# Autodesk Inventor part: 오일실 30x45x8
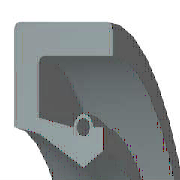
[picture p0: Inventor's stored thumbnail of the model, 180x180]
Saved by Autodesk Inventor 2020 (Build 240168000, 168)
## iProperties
Created: 2012-02
Part Number: 오일실 30x45x8
Material: 고무
Document SubType Name: Modeling
Standard: JIS B 2402
Designer: mdu-01
Standards Organization: JIS
Language: ko-KR
Size Designation: 30 45 8 A
Categories: <MemberInstance><Categories><Category DisplayName="샤프트 부품" InternalName="7f7aeb1f-a693-4053-b835-cee3144e0d98" Mnemonic="SHFT"><Category DisplayName="실링" Intern
Density: 0.93 g/cm^3
Appearance: Rubber-Black
IsCustomPart: 1
Author: mdu-01
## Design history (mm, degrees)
body "Solid1"
revolve "회전1" stored, may be unused: angle "d33" = 360 deg
fillet "모깎기1" dims "d34" = 0.4 (= 0.05 x b)
sketch "스케치2"
  geometry: L1 (16.821, -5.895)-(17.526, -8); L2 (16.071, -5.2)-(16.821, -5.895); L3 (15, -2)-(16.071, -5.2); L4 (16, -1)-(15, -2); L5 (17.676, -1)-(16, -1); L6 (17.676, -1.8)-(17.676, -1); L7 (17.676, -6)-(17.676, -3.4); L8 (19.5, -6)-(17.676, -6); L9 (21, -2)-(19.5, -6); L10 (21, 0)-(21, -2); L11 (22.5, 0)-(21, 0); L12 (22.5, -8)-(22.5, 0); L13 (17.526, -8)-(22.5, -8); L14 (0, -9.6)-(0, 1.6) reference; L15 (28, 0)-(14, 0) reference; A1 r 0.8 centre (17.676, -2.6) between (17.676, -3.4) and (17.676, -1.8)
  constraints: 26 end point, 4 horizontal, 4 vertical, 2 point on circle, 1 centre point, 1 collinear, 1 parallel
  dimensions: "d2" = 8 distance of L12.start L11.start (= b); "d4" = 1 vertical distance of L10.start L5.start (= 0.125 x b); "d6" = 1.5 distance of L11.start L10.start (= 0.1 x dd - 0.1 x Diam); "d8" = 2 distance of L10.start L9.start (= 0.25 x b); "d10" = 2 vertical distance of L8.start L1.end (= 0.25 x b); "d12" = 1.5 horizontal distance of L9.start L8.start (= 0.1 x dd - 0.1 x Diam); "d14" = 0.8 radius of A1 (= 0.1 x b); "d16" = 0 horizontal distance of A1.centre L7.end; "d18" = 0.8 distance of L6.start L5.start (= 0.1 x b); "d20" = 1 horizontal distance of L4.start L3.start (= 0.0666667 x dd - 0.0666667 x Diam); "d22" = 0.15 horizontal distance of L7.start L1.end (= 0.01 x dd - 0.01 x Diam); "d24" = 1 horizontal distance of L4.start L3.start (= 0.125 x b); "d26" = 3.2 vertical distance of L3.start L2.start (= 0.4 x b); "d28" = 1.07143 horizontal distance of L3.start L2.start (= 0.0714286 x dd - 0.0714286 x Diam); "d30" = 2.10526 vertical distance of L1.start L1.end (= 0.263158 x b); "d32" = 0.75 horizontal distance of L2.start L1.start (= 0.05 x dd - 0.05 x Diam); "d37" = 0 distance between parallel lines of L15 L11; "d38" = 22.5 distance between parallel lines of L14 L12 (= 0.5 x dd); "d39" = 15 distance from line of L14 L3.start (= 0.5 x Diam)
other parameters: "dd" = 45 [user parameter; used in 7 equation terms], "b" = 8 [user parameter; used in 10 equation terms], "d1" = 8 (derived), "d3" = 1 (derived), "d5" = 2 (derived), "d7" = 2 (derived), "d9" = 2 (derived), "d11" = 2 (derived), "d13" = 0.8 (derived), "d15" = 0 (derived), "d17" = 0.8 (derived), "d19" = 1.33333 (derived), "d21" = 0.2 (derived), "d23" = 1 (derived), "d25" = 3.2 (derived), "d27" = 1.42857 (derived), "d29" = 2.10526 (derived), "d31" = 1 (derived), "d40" = 0
